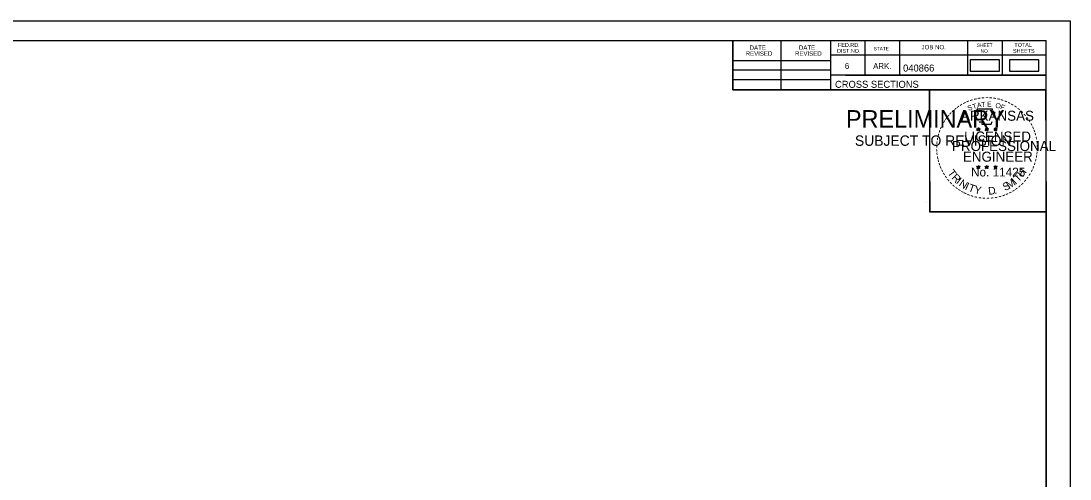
# Model space of a CAD drawing. Extents: x 1370565 to 1374448, y 301010 to 304637.
# Drawn here: x 1373322 to 1373531.7, y 303980.2 to 304071.7 of the extents above; entities that cross this region are included whole.
import ezdxf

# ---------------------------------------------------------------- set-up
doc = ezdxf.new("R2010")
doc.units = 0
for name, color, linetype in [('Default', 7, 'Continuous'), ('R_Border', 7, 'Continuous'), ('R_Border PE', 7, 'Continuous'), ('R_Border Prem', 7, 'Continuous'), ('R_Drive', 7, 'Continuous'), ('R_No Plot', 7, 'Continuous')]:
    doc.layers.add(name, color=color, linetype=linetype)

msp = doc.modelspace()

# ---------------------------------------------------------------- linework, layer by layer
at = {"layer": 'Default'}
msp.add_lwpolyline([(1373511.81, 304061.66), (1373517.64, 304061.66), (1373517.64, 304063.97), (1373511.81, 304063.97)], close=True, dxfattribs=at)
at = {"layer": 'R_Border'}
for p, q in [((1373210.81, 304067.81), (1373526.99, 304067.81)), ((1373363.33, 304067.55), (1373363.33, 304067.55)), ((1373363.33, 304067.55), (1373363.33, 304067.55)), ((1373464.35, 304057.93), (1373464.35, 304067.81)), ((1373474.03, 304057.93), (1373474.03, 304067.81)), ((1373483.89, 304067.81), (1373483.89, 304057.93)), ((1373490.73, 304067.81), (1373490.73, 304060.87)), ((1373497.67, 304067.81), (1373497.67, 304060.87)), ((1373511.25, 304067.81), (1373511.25, 304060.87)), ((1373518.19, 304067.81), (1373518.19, 304060.87)), ((1373526.99, 303862.35), (1373526.99, 304067.81)), ((1373464.35, 304063.79), (1373483.89, 304063.79)), ((1373526.99, 304064.87), (1373483.89, 304064.87)), ((1373526.99, 304064.89), (1373526.99, 304064.89)), ((1373464.35, 304061.93), (1373483.89, 304061.93)), ((1373464.35, 304059.99), (1373483.89, 304059.99)), ((1373526.99, 304060.87), (1373483.89, 304060.87)), ((1373486.85, 304060.87), (1373526.99, 304060.87)), ((1373526.99, 304057.93), (1373464.35, 304057.93))]:
    msp.add_line(p, q, dxfattribs=at)
at = {"layer": 'R_Border PE'}
for p, q in [((1373513.43, 304050.44), (1373513.39, 304050.19)), ((1373513.43, 304050.08), (1373513.43, 304050.44)), ((1373513.43, 304050.44), (1373513.48, 304050.19)), ((1373515.1, 304050.44), (1373515.06, 304050.19)), ((1373515.1, 304050.08), (1373515.1, 304050.44)), ((1373515.1, 304050.44), (1373515.15, 304050.19)), ((1373516.86, 304050.43), (1373516.82, 304050.18)), ((1373516.86, 304050.07), (1373516.86, 304050.43)), ((1373516.86, 304050.43), (1373516.91, 304050.18)), ((1373513.08, 304050.19), (1373513.43, 304050.08)), ((1373513.08, 304050.19), (1373513.33, 304050.14)), ((1373513.08, 304050.19), (1373513.32, 304050.07)), ((1373513.21, 304049.78), (1373513.43, 304050.08)), ((1373513.21, 304049.78), (1373513.34, 304050.03)), ((1373513.21, 304049.78), (1373513.43, 304050)), ((1373513.78, 304050.19), (1373513.43, 304050.08)), ((1373513.64, 304049.78), (1373513.43, 304050.08)), ((1373513.64, 304049.78), (1373513.43, 304050)), ((1373513.78, 304050.19), (1373513.49, 304050.14)), ((1373513.64, 304049.78), (1373513.5, 304050.07)), ((1373513.78, 304050.19), (1373513.57, 304050.09)), ((1373514.75, 304050.19), (1373515.1, 304050.08)), ((1373514.75, 304050.19), (1373515, 304050.14)), ((1373514.75, 304050.19), (1373514.99, 304050.07)), ((1373514.88, 304049.78), (1373515.1, 304050.08)), ((1373514.88, 304049.78), (1373515.01, 304050.03)), ((1373514.88, 304049.78), (1373515.1, 304050)), ((1373515.45, 304050.19), (1373515.1, 304050.08)), ((1373515.31, 304049.78), (1373515.1, 304050.08)), ((1373515.31, 304049.78), (1373515.1, 304050)), ((1373515.45, 304050.19), (1373515.16, 304050.14)), ((1373515.31, 304049.78), (1373515.17, 304050.07)), ((1373515.45, 304050.19), (1373515.24, 304050.09)), ((1373516.51, 304050.18), (1373516.86, 304050.07)), ((1373516.51, 304050.18), (1373516.77, 304050.13)), ((1373516.51, 304050.18), (1373516.75, 304050.06)), ((1373516.65, 304049.77), (1373516.86, 304050.07)), ((1373516.65, 304049.77), (1373516.77, 304050.01)), ((1373516.65, 304049.77), (1373516.86, 304049.99)), ((1373517.21, 304050.18), (1373516.86, 304050.07)), ((1373517.08, 304049.77), (1373516.86, 304050.07)), ((1373517.08, 304049.77), (1373516.86, 304049.98)), ((1373517.21, 304050.18), (1373516.92, 304050.13)), ((1373517.08, 304049.77), (1373516.94, 304050.06)), ((1373517.21, 304050.18), (1373517.01, 304050.08)), ((1373513.08, 304042.62), (1373513.42, 304042.51)), ((1373513.08, 304042.62), (1373513.33, 304042.57)), ((1373513.08, 304042.62), (1373513.31, 304042.49)), ((1373513.21, 304042.21), (1373513.42, 304042.51)), ((1373513.21, 304042.21), (1373513.33, 304042.45)), ((1373513.21, 304042.21), (1373513.42, 304042.43)), ((1373513.42, 304042.87), (1373513.38, 304042.62)), ((1373513.42, 304042.51), (1373513.42, 304042.87)), ((1373513.42, 304042.87), (1373513.47, 304042.62)), ((1373513.77, 304042.62), (1373513.42, 304042.51)), ((1373513.64, 304042.21), (1373513.42, 304042.51)), ((1373513.64, 304042.21), (1373513.42, 304042.42)), ((1373513.77, 304042.62), (1373513.49, 304042.57)), ((1373513.64, 304042.21), (1373513.5, 304042.5)), ((1373513.77, 304042.62), (1373513.57, 304042.51)), ((1373514.74, 304042.62), (1373515.09, 304042.51)), ((1373514.74, 304042.62), (1373515, 304042.57)), ((1373514.74, 304042.62), (1373514.98, 304042.49)), ((1373514.88, 304042.21), (1373515.09, 304042.51)), ((1373514.88, 304042.21), (1373515, 304042.45)), ((1373514.88, 304042.21), (1373515.09, 304042.43)), ((1373515.09, 304042.87), (1373515.05, 304042.62)), ((1373515.09, 304042.51), (1373515.09, 304042.87)), ((1373515.09, 304042.87), (1373515.14, 304042.62)), ((1373515.44, 304042.62), (1373515.09, 304042.51)), ((1373515.31, 304042.21), (1373515.09, 304042.51)), ((1373515.31, 304042.21), (1373515.09, 304042.42)), ((1373515.44, 304042.62), (1373515.15, 304042.57)), ((1373515.31, 304042.21), (1373515.17, 304042.5)), ((1373515.44, 304042.62), (1373515.24, 304042.51)), ((1373516.51, 304042.61), (1373516.86, 304042.5)), ((1373516.51, 304042.61), (1373516.76, 304042.56)), ((1373516.51, 304042.61), (1373516.75, 304042.48)), ((1373516.64, 304042.2), (1373516.86, 304042.5)), ((1373516.64, 304042.2), (1373516.77, 304042.44)), ((1373516.64, 304042.2), (1373516.86, 304042.42)), ((1373516.86, 304042.86), (1373516.82, 304042.61)), ((1373516.86, 304042.5), (1373516.86, 304042.86)), ((1373516.86, 304042.86), (1373516.91, 304042.61)), ((1373517.21, 304042.61), (1373516.86, 304042.5)), ((1373517.07, 304042.2), (1373516.86, 304042.5)), ((1373517.07, 304042.2), (1373516.86, 304042.41)), ((1373517.21, 304042.61), (1373516.92, 304042.56)), ((1373517.07, 304042.2), (1373516.94, 304042.49)), ((1373517.21, 304042.61), (1373517, 304042.5))]:
    msp.add_line(p, q, dxfattribs=at)
for points in [[(1373513.12, 304054.07), (1373513.39, 304053.24)], [(1373516.63, 304053.15), (1373516.77, 304053.43), (1373516.09, 304053.41), (1373516.24, 304054.07), (1373513.12, 304054.07)], [(1373513.43, 304050.44), (1373513.64, 304049.78), (1373513.08, 304050.19), (1373513.78, 304050.19), (1373513.21, 304049.78), (1373513.43, 304050.44)], [(1373513.61, 304051.64), (1373513.61, 304051.56), (1373514.18, 304051.54), (1373514.12, 304051.07), (1373515.99, 304051.07), (1373516.19, 304051.6)], [(1373515.1, 304050.44), (1373515.31, 304049.78), (1373514.75, 304050.19), (1373515.45, 304050.19), (1373514.88, 304049.78), (1373515.1, 304050.44)], [(1373516.86, 304050.43), (1373517.08, 304049.77), (1373516.51, 304050.18), (1373517.21, 304050.18), (1373516.65, 304049.77), (1373516.86, 304050.43)], [(1373513.42, 304042.87), (1373513.64, 304042.21), (1373513.08, 304042.62), (1373513.77, 304042.62), (1373513.21, 304042.21), (1373513.42, 304042.87)], [(1373515.09, 304042.87), (1373515.31, 304042.21), (1373514.74, 304042.62), (1373515.44, 304042.62), (1373514.88, 304042.21), (1373515.09, 304042.87)], [(1373516.86, 304042.86), (1373517.07, 304042.2), (1373516.51, 304042.61), (1373517.21, 304042.61), (1373516.64, 304042.2), (1373516.86, 304042.86)]]:
    msp.add_lwpolyline(points, dxfattribs=at)
for centre, radius in [((1373513.43, 304050.08), 0.172), ((1373513.43, 304050.08), 0.145), ((1373513.43, 304050.08), 0.116), ((1373513.43, 304050.08), 0.0991), ((1373513.43, 304050.08), 0.0747), ((1373513.43, 304050.08), 0.0495), ((1373513.43, 304050.08), 0.0296), ((1373515.1, 304050.08), 0.172), ((1373515.1, 304050.08), 0.145), ((1373515.1, 304050.08), 0.116), ((1373515.1, 304050.08), 0.0991), ((1373515.1, 304050.08), 0.0747), ((1373515.1, 304050.08), 0.0495), ((1373515.1, 304050.08), 0.0296), ((1373516.86, 304050.07), 0.172), ((1373516.86, 304050.07), 0.145), ((1373516.86, 304050.07), 0.116), ((1373516.86, 304050.07), 0.0991), ((1373516.86, 304050.07), 0.0747), ((1373516.86, 304050.07), 0.0495), ((1373516.86, 304050.07), 0.0296), ((1373513.42, 304042.5), 0.172), ((1373513.42, 304042.5), 0.145), ((1373513.42, 304042.5), 0.116), ((1373513.42, 304042.5), 0.0991), ((1373513.42, 304042.5), 0.0747), ((1373513.42, 304042.5), 0.0495), ((1373513.42, 304042.5), 0.0296), ((1373515.09, 304042.5), 0.172), ((1373515.09, 304042.5), 0.145), ((1373515.09, 304042.5), 0.116), ((1373515.09, 304042.5), 0.0991), ((1373515.09, 304042.5), 0.0747), ((1373515.09, 304042.5), 0.0495), ((1373515.09, 304042.5), 0.0296), ((1373516.86, 304042.49), 0.172), ((1373516.86, 304042.49), 0.145), ((1373516.86, 304042.49), 0.116), ((1373516.86, 304042.49), 0.0991), ((1373516.86, 304042.49), 0.0747), ((1373516.86, 304042.49), 0.0495), ((1373516.86, 304042.49), 0.0296)]:
    msp.add_circle(centre, radius, dxfattribs=at)
at = {"layer": 'R_Drive'}
msp.add_lwpolyline([(1373519.68, 304061.67), (1373525.51, 304061.67), (1373525.51, 304063.98), (1373519.68, 304063.98)], close=True, dxfattribs=at)
at = {"layer": 'R_No Plot'}
for p, q in [((1373198.41, 304071.71), (1373531.75, 304071.71)), ((1373503.03, 304035.48), (1373503.03, 304035.48))]:
    msp.add_line(p, q, dxfattribs=at)
for points in [[(1373198.41, 304071.71), (1373531.75, 304071.71), (1373531.75, 303858.37), (1373198.41, 303858.37)], [(1373444.73, 304067.81), (1373464.35, 304067.81), (1373464.35, 304057.93), (1373480.47, 304057.93), (1373503.67, 304057.93), (1373503.67, 304033.6), (1373526.99, 304033.6), (1373526.99, 303862.35), (1373210.81, 303862.35), (1373210.81, 304067.81)], [(1373503.67, 304057.93), (1373526.87, 304057.93), (1373526.99, 304033.6), (1373503.79, 304033.6)]]:
    msp.add_lwpolyline(points, close=True, dxfattribs=at)

# ---------------------------------------------------------------- texts
at = {"layer": 'R_Border'}
for s, height, p in [('FED.RD.', 0.782, (1373485.37, 304066.53)), ('SHEET', 0.684, (1373513.11, 304066.53)), ('TOTAL', 0.782, (1373520.63, 304066.53)), ('REVISED', 0.879, (1373466.91, 304064.77)), ('DATE', 0.879, (1373467.69, 304065.95)), ('REVISED', 0.879, (1373476.77, 304064.77)), ('DATE', 0.879, (1373477.55, 304065.95)), ('DIST.NO.', 0.782, (1373485.17, 304065.35)), ('STATE', 0.684, (1373492.49, 304065.85)), ('JOB NO.', 0.879, (1373502.07, 304066.05)), ('NO.', 0.684, (1373513.89, 304065.35)), ('SHEETS', 0.782, (1373520.35, 304065.35)), ('6', 1.17, (1373486.73, 304062.13)), ('ARK.', 1.172, (1373492.39, 304062.13)), ('040866', 1.4, (1373498.37, 304061.61)), ('CROSS SECTIONS', 1.4, (1373484.76, 304058.36))]:
    msp.add_text(s, height=height, rotation=360, dxfattribs=at).set_placement(p)
at = {"layer": 'R_Border PE'}
for s, height, rotation, p in [('-', 1.6, 36.2317, (1373509.43, 304053.84)), ('-', 1.6, 34.0636, (1373510, 304054.24)), ('-', 1.6, 28.7918, (1373510.6, 304054.61)), ('-', 1.6, 24.3072, (1373511.23, 304054.93)), ('S', 1, 21.594, (1373511.48, 304053.75)), ('-', 1.6, 19.1761, (1373511.87, 304055.19)), ('T', 1, 16.4036, (1373512.39, 304054.08)), ('-', 1.6, 13.6301, (1373512.62, 304055.44)), ('A', 1, 11.2132, (1373513.22, 304054.33)), ('-', 1.6, 10.2193, (1373513.3, 304055.6)), ('T', 1, 6.0228, (1373514.06, 304054.49)), ('-', 1.6, 5.8968, (1373514.03, 304055.71)), ('-', 1.6, 0.1862, (1373514.8, 304055.78)), ('E', 1, 0.8323, (1373515.17, 304054.6)), ('-', 1.6, 357.743, (1373515.52, 304055.77)), ('-', 1.6, 352.1617, (1373516.26, 304055.71)), ('O', 1, 350.4515, (1373516.77, 304054.39)), ('-', 1.6, 347.2049, (1373516.98, 304055.6)), ('F', 1, 340.0707, (1373517.73, 304054.17)), ('-', 1.6, 342.3362, (1373517.62, 304055.44)), ('-', 1.6, 337.8551, (1373518.35, 304055.22)), ('-', 1.6, 334.1211, (1373518.98, 304054.95)), ('-', 1.6, 329.6409, (1373519.56, 304054.66)), ('-', 1.6, 325.8627, (1373520.21, 304054.3)), ('-', 1.6, 50.6142, (1373507.67, 304052.08)), ('-', 1.6, 48.423, (1373508.07, 304052.57)), ('-', 1.6, 42.9622, (1373508.52, 304053.05)), ('-', 1.6, 38.9507, (1373508.95, 304053.47)), ('ARKANSAS', 2, 360, (1373509.97, 304051.78)), ('-', 1.6, 320.5297, (1373520.82, 304053.88)), ('-', 1.6, 315.5786, (1373521.42, 304053.39)), ('-', 1.6, 309.8797, (1373521.98, 304052.84)), ('-', 1.6, 306.6522, (1373522.51, 304052.24)), ('-', 1.6, 67.7743, (1373506.36, 304049.77)), ('-', 1.6, 62.8713, (1373506.62, 304050.38)), ('-', 1.6, 58.0706, (1373506.93, 304050.99)), ('-', 1.6, 54.2325, (1373507.25, 304051.52)), ('-', 1.4, 303.6753, (1373523, 304051.67)), ('-', 1.6, 299.6684, (1373523.31, 304051.06)), ('-', 1.6, 294.6628, (1373523.64, 304050.45)), ('-', 1.6, 81.2013, (1373505.81, 304047.71)), ('-', 1.6, 75.461, (1373505.94, 304048.42)), ('-', 1.6, 72.3945, (1373506.14, 304049.14)), ('LICENSED', 2, 360, (1373510.57, 304047.63)), ('DWB', 0.01, 360, (1373513.42, 304050.07)), ('DWB', 0.01, 360, (1373515.09, 304050.07)), ('DWB', 0.01, 360, (1373516.85, 304050.06)), ('-', 1.6, 290.5728, (1373523.9, 304049.87)), ('-', 1.6, 285.1233, (1373524.13, 304049.29)), ('-', 1.6, 280.5493, (1373524.33, 304048.55)), ('-', 1.6, 89.0622, (1373505.71, 304046.32)), ('-', 1.6, 85.1863, (1373505.73, 304047.02)), ('PROFESSIONAL', 2, 360, (1373508.15, 304045.73)), ('-', 1.6, 276.5962, (1373524.49, 304047.78)), ('-', 1.6, 274.3301, (1373524.55, 304047.06)), ('-', 1.6, 269.9407, (1373524.59, 304046.43)), ('-', 1.6, 94.1959, (1373505.74, 304045.59)), ('-', 1.6, 98.9479, (1373505.81, 304044.92)), ('-', 1.6, 101.7149, (1373505.95, 304044.19)), ('ENGINEER', 2, 360, (1373510.33, 304043.6)), ('-', 1.6, 255.7626, (1373524.39, 304044.43)), ('-', 1.6, 260.9953, (1373524.5, 304045.11)), ('-', 1.6, 263.5172, (1373524.57, 304045.76)), ('-', 1.6, 105.4578, (1373506.11, 304043.6)), ('-', 1.6, 109.0874, (1373506.33, 304042.97)), ('-', 1.6, 114.0643, (1373506.58, 304042.37)), ('-', 1.6, 115.7289, (1373506.89, 304041.75)), ('T', 1.54, 306.0406, (1373507.18, 304041.34)), ('No. 11425', 1.757, 360, (1373511.96, 304040.65)), ('DWB', 0.01, 360, (1373513.41, 304042.5)), ('DWB', 0.01, 360, (1373515.08, 304042.5)), ('DWB', 0.01, 360, (1373516.85, 304042.49)), ('H', 1.54, 54.6088, (1373522.3, 304040.38)), ('-', 1.6, 244.6197, (1373523.72, 304042.41)), ('-', 1.6, 247.8887, (1373523.98, 304043.04)), ('-', 1.6, 252.8681, (1373524.2, 304043.71)), ('-', 1.6, 120.4471, (1373507.24, 304041.17)), ('-', 1.6, 125.8934, (1373507.65, 304040.6)), ('-', 1.6, 130.7181, (1373508.11, 304040.05)), ('R', 1.54, 314.005, (1373507.95, 304040.3)), ('I', 1.54, 321.9694, (1373508.85, 304039.36)), ('N', 1.54, 326.5002, (1373509.41, 304038.89)), ('M', 1.54, 32.6563, (1373519.57, 304038.11)), ('I', 1.54, 42.1136, (1373520.85, 304038.96)), ('T', 1.54, 46.6444, (1373521.41, 304039.44)), ('-', 1.6, 231.2538, (1373522.49, 304040.44)), ('-', 1.6, 233.8452, (1373522.92, 304041)), ('-', 1.6, 239.0712, (1373523.33, 304041.66)), ('-', 1.6, 134.2238, (1373508.62, 304039.51)), ('-', 1.6, 138.9338, (1373509.15, 304039.04)), ('-', 1.6, 144.6463, (1373509.71, 304038.64)), ('-', 1.6, 148.0898, (1373510.27, 304038.27)), ('I', 1.54, 335.3603, (1373510.62, 304038.11)), ('T', 1.54, 339.8912, (1373511.28, 304037.78)), ('Y', 1.54, 347.8556, (1373512.5, 304037.33)), ('D', 1.54, 6.3969, (1373515.48, 304036.97)), ('S', 1.54, 26.9312, (1373518.73, 304037.71)), ('-', 1.6, 212.2491, (1373520.41, 304038.51)), ('-', 1.6, 215.7363, (1373520.94, 304038.89)), ('-', 1.6, 221.0851, (1373521.49, 304039.37)), ('-', 1.6, 225.7653, (1373522.01, 304039.87)), ('-', 1.6, 151.5704, (1373510.85, 304037.94)), ('-', 1.6, 154.6002, (1373511.37, 304037.69)), ('-', 1.6, 158.5612, (1373511.99, 304037.44)), ('-', 1.6, 162.7983, (1373512.68, 304037.23)), ('-', 1.6, 167.5555, (1373513.39, 304037.06)), ('-', 1.6, 173.1155, (1373514.17, 304036.95)), ('-', 1.6, 176.5183, (1373514.91, 304036.9)), ('-', 1.6, 181.5918, (1373515.66, 304036.92)), ('-', 1.6, 185.8167, (1373516.47, 304037)), ('-', 1.6, 191.2858, (1373517.2, 304037.13)), ('.', 1.54, 13.7642, (1373516.68, 304037.1)), ('-', 1.6, 195.4743, (1373517.93, 304037.33)), ('-', 1.6, 200.7184, (1373518.61, 304037.57)), ('-', 1.6, 204.2516, (1373519.23, 304037.84)), ('-', 1.6, 207.3568, (1373519.85, 304038.16))]:
    msp.add_text(s, height=height, rotation=rotation, dxfattribs=at).set_placement(p)
at = {"layer": 'R_Border Prem'}
for s, height, p in [('PRELIMINARY', 3.5, (1373486.95, 304050.4)), ('DWB', 0.01, (1373487.69, 304052.25)), ('SUBJECT TO REVISION', 2.0751, (1373488.75, 304046.77))]:
    msp.add_text(s, height=height, rotation=360, dxfattribs=at).set_placement(p)

doc.saveas('drawing.dxf')
